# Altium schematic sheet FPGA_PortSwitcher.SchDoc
size A4; Organization: Altium Limited; Address1: L3, 12a Rodborough Rd; Address2: Frenchs Forest; Address3: NSW; Address4: Australia 2086; DocumentNumber: 1; SheetNumber: 1; SheetTotal: 4
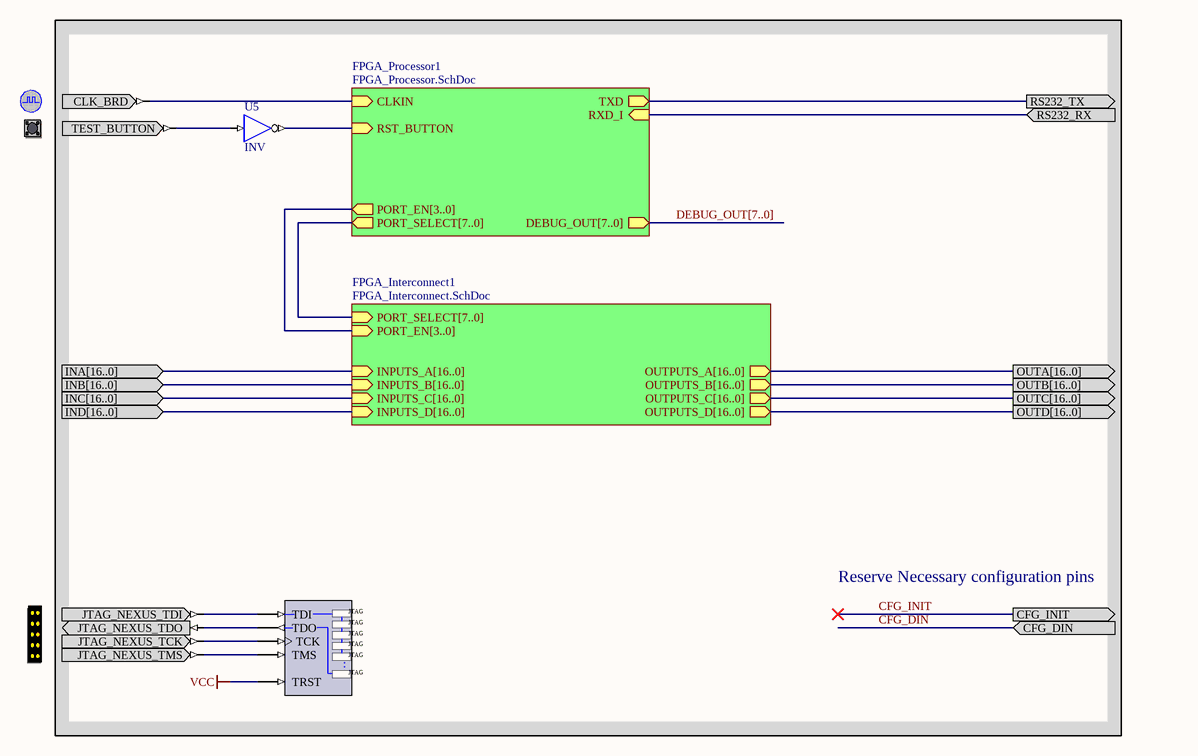
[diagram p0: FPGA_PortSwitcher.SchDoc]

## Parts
(Parts that share a designator on the sheet are numbered #1, #2 ... from top to bottom, then left to right.)
?#1  CLOCK_BOARD  (value not drawn)
?#2  TEST_BUTTON  (value not drawn)
?#3  NEXUS_JTAG_CONNECTOR  (value not drawn)
NEXUS_JTAG_PORT  NEXUS_JTAG_PORT  (value not drawn)
U5  INV

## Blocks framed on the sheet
Reserve Necessary configuration pins: ?#1-?#3 NEXUS_JTAG_PORT U5

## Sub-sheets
FPGA_Interconnect1 = FPGA_Interconnect.SchDoc: PORT_SELECT[7..0] (in), OUTPUTS_D[16..0] (out), OUTPUTS_C[16..0] (out), OUTPUTS_B[16..0] (out), OUTPUTS_A[16..0] (out), PORT_EN[3..0] (in), INPUTS_A[16..0] (in), INPUTS_B[16..0] (in), INPUTS_C[16..0] (in), INPUTS_D[16..0] (in)
FPGA_Processor1 = FPGA_Processor.SchDoc: TXD (out), RXD_I (in), CLKIN (in), RST_BUTTON (in), PORT_SELECT[7..0] (out), PORT_EN[3..0] (out), DEBUG_OUT[7..0] (out)

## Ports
CFG_DIN (in), CFG_INIT (out), INA[16..0] (in), INB[16..0] (in), INC[16..0] (in), IND[16..0] (in), OUTA[16..0] (out), OUTB[16..0] (out), OUTC[16..0] (out), OUTD[16..0] (out), RS232_RX (in), RS232_TX (out)

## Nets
VCC: NEXUS_JTAG_PORT.TRST
RS232_RX: port RS232_RX, sheet FPGA_Processor1/RXD_I
RS232_TX: port RS232_TX, sheet FPGA_Processor1/TXD
Net?#1_CLK_BRD: ?#1.CLK_BRD ; sheet FPGA_Processor1/CLKIN
Net?#2_TEST_BUTTON: ?#2.TEST_BUTTON U5.I
Net?#3_JTAG_NEXUS_TCK: ?#3.JTAG_NEXUS_TCK NEXUS_JTAG_PORT.TCK
Net?#3_JTAG_NEXUS_TDI: ?#3.JTAG_NEXUS_TDI NEXUS_JTAG_PORT.TDI
Net?#3_JTAG_NEXUS_TDO: ?#3.JTAG_NEXUS_TDO NEXUS_JTAG_PORT.TDO
Net?#3_JTAG_NEXUS_TMS: ?#3.JTAG_NEXUS_TMS NEXUS_JTAG_PORT.TMS
NetU5_O: U5.O ; sheet FPGA_Processor1/RST_BUTTON

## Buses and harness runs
bus DEBUG_OUT[7..0] = sheet FPGA_Processor1/DEBUG_OUT[7..0]
bus port INA[16..0] = sheet FPGA_Interconnect1/INPUTS_A[16..0]
bus port INB[16..0] = sheet FPGA_Interconnect1/INPUTS_B[16..0]
bus port INC[16..0] = sheet FPGA_Interconnect1/INPUTS_C[16..0]
bus port IND[16..0] = sheet FPGA_Interconnect1/INPUTS_D[16..0]
bus port OUTA[16..0] = sheet FPGA_Interconnect1/OUTPUTS_A[16..0]
bus port OUTB[16..0] = sheet FPGA_Interconnect1/OUTPUTS_B[16..0]
bus port OUTC[16..0] = sheet FPGA_Interconnect1/OUTPUTS_C[16..0]
bus port OUTD[16..0] = sheet FPGA_Interconnect1/OUTPUTS_D[16..0]
bus sheet FPGA_Interconnect1/PORT_EN[3..0] = sheet FPGA_Processor1/PORT_EN[3..0]
bus sheet FPGA_Interconnect1/PORT_SELECT[7..0] = sheet FPGA_Processor1/PORT_SELECT[7..0]

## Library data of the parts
?#1 = CLOCK_BOARD: Global System Clock Supply; PortComponent: True
?#2 = TEST_BUTTON: Test Button; PortComponent: True
?#3 = NEXUS_JTAG_CONNECTOR: JTAG Port; PortComponent: True
NEXUS_JTAG_PORT = NEXUS_JTAG_PORT: Soft Nexus-Chain Connector; NEXUS_JTAG_CONNECTOR: True
U5 = INV: Inverter; ArchiveName: GENERIC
